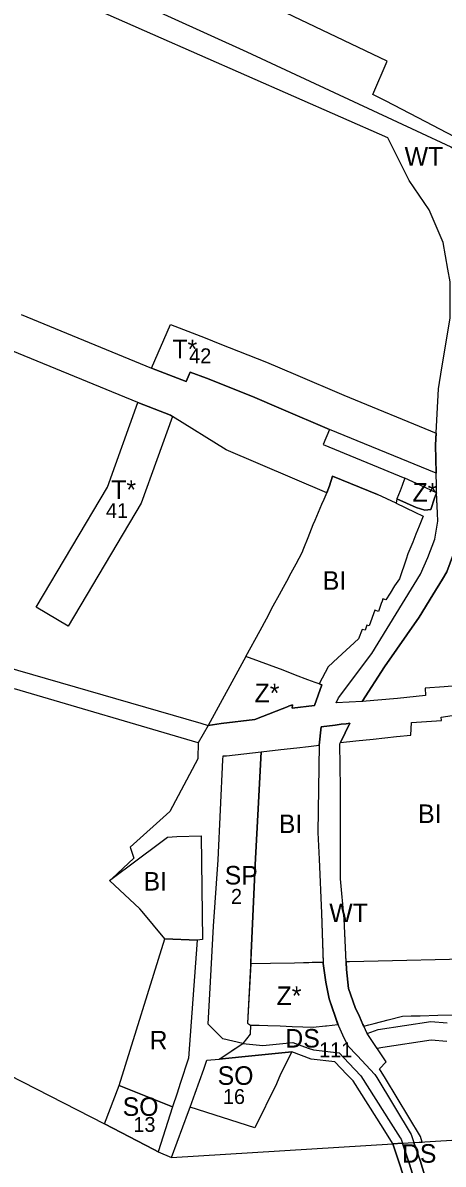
# Model space of a CAD drawing. Extents: x -521621 to -516769, y -1190068 to -1185078.
# Drawn here: x -520203 to -519977, y -1187500 to -1186885 of the extents above; entities that cross this region are included whole.
import ezdxf

# ---------------------------------------------------------------- set-up
doc = ezdxf.new("R2010")
doc.units = 0
for name, color, linetype in [('bydleni_s', 7, 'Continuous'), ('fpl_id', 7, 'Continuous'), ('rekreace_s', 7, 'Continuous'), ('s_zelen_s', 7, 'Continuous'), ('sm_vyuziti_n', 7, 'Continuous'), ('v_infrastr_n', 7, 'Continuous'), ('v_infrastr_s', 7, 'Continuous'), ('voda_s', 7, 'Continuous')]:
    doc.layers.add(name, color=color, linetype=linetype)

msp = doc.modelspace()

# ---------------------------------------------------------------- linework, layer by layer
at = {"layer": 'bydleni_s'}
for p, q in [((-519995.52, -1187170.82), (-519996.45, -1187173.61)), ((-520062.6, -1187188.74), (-520060.79, -1187185.41)), ((-520002.68, -1187187.93), (-520005.12, -1187191.92)), ((-520022.2, -1187216.47), (-520033.21, -1187226.78)), ((-520043.4, -1187240.82), (-520045.38, -1187240.09)), ((-520023.56, -1187271.54), (-520014.27, -1187270.57)), ((-520014.27, -1187270.57), (-520001.7, -1187269.26)), ((-520001.7, -1187269.26), (-519993.91, -1187268.44)), ((-520077.74, -1187338.31), (-520075.98, -1187304.68))]:
    msp.add_line(p, q, dxfattribs=at)
for points in [[(-520052.48, -1187170.02), (-520051.52, -1187167.64), (-520049.24, -1187161.96), (-520046.54, -1187155.01), (-520045.46, -1187152.58), (-520041.85, -1187144.05), (-520040.71, -1187141.36), (-520039.62, -1187138.78), (-520037.66, -1187134.14), (-520036.08, -1187128.81), (-520011.85, -1187138.77)], [(-519991.84, -1187148.2), (-519987.24, -1187150.36), (-519989.45, -1187155.81), (-519991.19, -1187160.12)], [(-519991.19, -1187160.12), (-519992.91, -1187164.38), (-519995.52, -1187170.82)], [(-519976.92, -1187184.39), (-519974.6, -1187180.49), (-519967.44, -1187161.06), (-519964.45, -1187159.95)], [(-520058.38, -1187180.94), (-520055.75, -1187176.08), (-520052.48, -1187170.02)], [(-519996.45, -1187173.61), (-519999.98, -1187184.21), (-520002.68, -1187187.93)], [(-520060.79, -1187185.41), (-520060.79, -1187185.41), (-520058.38, -1187180.94)], [(-519982.08, -1187192.81), (-519976.92, -1187184.39)], [(-520062.74, -1187233.45), (-520082.78, -1187226.03), (-520075.16, -1187212), (-520071.75, -1187205.69), (-520068.02, -1187198.79), (-520064.75, -1187192.74), (-520062.6, -1187188.74)], [(-520005.12, -1187191.92), (-520007.33, -1187195.55), (-520009.09, -1187194.99), (-520009.46, -1187196.2)], [(-520009.46, -1187196.2), (-520009.9, -1187197.54), (-520011.32, -1187201.87), (-520013.37, -1187201.13)], [(-519989.47, -1187204.85), (-519982.08, -1187192.81)], [(-520013.37, -1187201.13), (-520016.34, -1187209.5), (-520017.65, -1187209.12), (-520018.58, -1187211.91), (-520020.16, -1187211.54), (-520022.2, -1187216.47)], [(-520008.16, -1187231.72), (-519989.47, -1187204.85)], [(-520033.21, -1187226.78), (-520038.38, -1187231.62), (-520043.4, -1187240.82)], [(-520045.38, -1187240.09), (-520049.49, -1187238.6), (-520056.14, -1187236.18), (-520062.74, -1187233.45)], [(-520001.09, -1187248.72), (-520020.12, -1187250.41), (-520008.16, -1187231.72)], [(-519986.28, -1187243.18), (-519985.96, -1187247.03), (-520001.09, -1187248.72)], [(-519976.06, -1187242.43), (-519986.28, -1187243.18)], [(-519977.48, -1187260.57), (-519977.63, -1187258.79), (-519964.67, -1187256.87)], [(-519993.91, -1187268.44), (-519993.6, -1187261.65), (-519977.48, -1187260.57)], [(-520031.82, -1187333.95), (-520031.88, -1187296.91), (-520032.11, -1187273.07), (-520031.78, -1187272.4), (-520023.56, -1187271.54)], [(-520075.98, -1187304.68), (-520075.98, -1187304.68), (-520074.47, -1187277.44), (-520063.98, -1187276.25)], [(-520063.98, -1187276.25), (-520055.4, -1187275.27), (-520049, -1187274.54)], [(-520049, -1187274.54), (-520043.26, -1187273.88), (-520044.03, -1187320.95), (-520043.37, -1187335.34)], [(-520154.87, -1187345.66), (-520129.41, -1187326.7), (-520124.93, -1187323.53), (-520119.96, -1187323.11), (-520106.84, -1187322.8), (-520106.45, -1187351)], [(-519928.48, -1187329.94), (-519927.32, -1187362.5), (-519925.74, -1187387.64), (-519950.01, -1187388.86), (-520026.94, -1187390.59)], [(-520069.46, -1187391.55), (-520080.18, -1187391.79), (-520079.87, -1187386.04), (-520077.74, -1187338.31)], [(-520043.37, -1187335.34), (-520042.02, -1187364.47), (-520041.12, -1187390.91)], [(-520026.94, -1187390.59), (-520028.75, -1187390.63), (-520029.79, -1187367.52), (-520031.8, -1187345.91), (-520031.82, -1187333.95)], [(-520138.59, -1187363.54), (-520139.86, -1187362), (-520156.34, -1187346.76), (-520154.87, -1187345.66)], [(-520106.45, -1187351), (-520106.07, -1187378.67), (-520109, -1187378.97), (-520126.44, -1187378.2), (-520138.59, -1187363.54)], [(-520056.6, -1187391.26), (-520069.46, -1187391.55)], [(-520041.12, -1187390.91), (-520056.6, -1187391.26)]]:
    msp.add_lwpolyline(points, dxfattribs=at)
at = {"layer": 'rekreace_s'}
msp.add_lwpolyline([(-520151.11, -1187457.31), (-520126.44, -1187378.2), (-520109, -1187378.97), (-520113.78, -1187442.56), (-520118.16, -1187456.2), (-520119.82, -1187461.37), (-520122.23, -1187468.86)], close=True, dxfattribs=at)
at = {"layer": 's_zelen_s'}
msp.add_line((-520082.78, -1187226.03), (-520103.06, -1187263.21), dxfattribs=at)
for points in [[(-519981.11, -1187140.81), (-519980.11, -1187137.79), (-519988.63, -1187133.88), (-519997.15, -1187129.97), (-519997.34, -1187130.46), (-519997.52, -1187130.94)], [(-519997.52, -1187130.94), (-519998.46, -1187133.42), (-519998.64, -1187133.89), (-519999.75, -1187136.84), (-520000.58, -1187139.01)], [(-520000.58, -1187139.01), (-520001.4, -1187141.18)], [(-520001.4, -1187141.18), (-519991.04, -1187145.71), (-519986.33, -1187147.13), (-519983.12, -1187146.86), (-519981.11, -1187140.81)], [(-520103.06, -1187263.21), (-520096.08, -1187262.17), (-520077.9, -1187259.98), (-520066.44, -1187255.49), (-520060, -1187252.97), (-520059.76, -1187252.88), (-520057.72, -1187252.08), (-520057.81, -1187253.94), (-520045.91, -1187252.54), (-520041.82, -1187241.39), (-520043.4, -1187240.82), (-520045.38, -1187240.09), (-520049.49, -1187238.6), (-520056.14, -1187236.18), (-520062.74, -1187233.45), (-520082.78, -1187226.03)], [(-519925.74, -1187387.64), (-519950.01, -1187388.86), (-520026.94, -1187390.59)], [(-520080.18, -1187391.79), (-520081.88, -1187423.69), (-520080.26, -1187424.69)], [(-520069.46, -1187391.55), (-520080.18, -1187391.79)], [(-520056.6, -1187391.26), (-520069.46, -1187391.55)], [(-520047.12, -1187391.05), (-520056.6, -1187391.26)], [(-520033.27, -1187424.46), (-520033.18, -1187424.47), (-520038.01, -1187410.61), (-520039.71, -1187401.51), (-520041.1, -1187391.48), (-520041.12, -1187390.91), (-520047.12, -1187391.05)], [(-520026.94, -1187390.59), (-520028.75, -1187390.63)], [(-520028.75, -1187390.63), (-520028.56, -1187394.83), (-520027.48, -1187405.02), (-520023.85, -1187415.2), (-520021.62, -1187420.14), (-520019.74, -1187424.33), (-520019.29, -1187425.32)], [(-520019.29, -1187425.32), (-520016.5, -1187424.59), (-520013.71, -1187423.87), (-520006.09, -1187421.89), (-519998.46, -1187419.91), (-519993.67, -1187419.79), (-519988.89, -1187419.68), (-519979.39, -1187419.45), (-519969.88, -1187419.22)], [(-520080.26, -1187424.69), (-520075.65, -1187424.83), (-520071.03, -1187424.98), (-520064.4, -1187425.2), (-520057.77, -1187425.41), (-520052.11, -1187425.59), (-520046.46, -1187425.77), (-520039.86, -1187425.11), (-520039.4, -1187425.07)], [(-520039.4, -1187425.07), (-520033.27, -1187424.46)]]:
    msp.add_lwpolyline(points, dxfattribs=at)
at = {"layer": 'sm_vyuziti_n'}
for points in [[(-520103.02, -1187424.15), (-520101.79, -1187401.47), (-520100.32, -1187371.37), (-520097.7, -1187335.57), (-520095.26, -1187281.75), (-520094.96, -1187279.59), (-520093.26, -1187279.59), (-520074.47, -1187277.44), (-520075.98, -1187304.68), (-520077.74, -1187338.31), (-520079.87, -1187386.04), (-520081.88, -1187423.69), (-520080.26, -1187424.69), (-520080.41, -1187429.63), (-520084.35, -1187434.57), (-520095.15, -1187432.18)], [(-520159, -1187477.9), (-520151.11, -1187457.31), (-520122.23, -1187468.86), (-520129.99, -1187493.02), (-520132.3, -1187491.79)]]:
    msp.add_lwpolyline(points, close=True, dxfattribs=at)
for points in [[(-520084.9, -1187441.83), (-520058.07, -1187439.16), (-520064.09, -1187451.2), (-520066.25, -1187456.45), (-520077.97, -1187480.04), (-520112.8, -1187468.95), (-520110.1, -1187461.43)], [(-520110.1, -1187461.43), (-520105.47, -1187448.5), (-520103.75, -1187443.71), (-520097.11, -1187443.05), (-520084.9, -1187441.83)]]:
    msp.add_lwpolyline(points, dxfattribs=at)
at = {"layer": 'v_infrastr_n'}
for p, q in [((-520093.34, -1187114.72), (-520122.36, -1187096.77)), ((-520039.2, -1187137.79), (-520093.34, -1187114.72)), ((-520036.08, -1187128.81), (-520037.66, -1187134.14)), ((-520037.66, -1187134.14), (-520039.2, -1187137.79))]:
    msp.add_line(p, q, dxfattribs=at)
for points in [[(-520203.84, -1187041.77), (-520133.61, -1187070.63), (-520114.98, -1187077.93), (-520112.74, -1187072.75), (-520104.09, -1187076.15), (-520079.22, -1187085.96), (-520063.84, -1187092.51), (-520037.69, -1187103.65), (-520041.14, -1187111.86), (-519997.15, -1187129.97), (-519997.34, -1187130.46), (-519997.52, -1187130.94), (-519998.46, -1187133.42)], [(-520122.36, -1187096.77), (-520123.45, -1187096.09), (-520140.91, -1187089.25), (-520212.35, -1187059.89)], [(-520001.85, -1187143.49), (-520011.85, -1187138.77), (-520036.08, -1187128.81)], [(-519998.46, -1187133.42), (-519998.64, -1187133.89), (-519999.75, -1187136.84), (-520000.58, -1187139.01), (-520001.4, -1187141.18), (-520001.85, -1187143.49)], [(-520848.97, -1187150.16), (-520815.24, -1187153.86), (-520804.3, -1187155.06), (-520795.33, -1187156.04), (-520786.18, -1187157.04), (-520784.85, -1187157.19), (-520159, -1187477.9), (-520132.3, -1187491.79), (-520129.99, -1187493.02), (-520122.89, -1187496.11), (-520003.64, -1187488.76), (-519999.44, -1187501.15), (-519986.81, -1187542.36), (-519985.87, -1187549.88), (-519983.1, -1187579.65), (-519979.33, -1187615.33), (-519966.43, -1187650.48), (-519963.31, -1187658.97), (-520250.83, -1187655.58), (-520830.3, -1187354.88)], [(-519974.58, -1187433.59), (-519982.91, -1187432.87), (-520009.06, -1187436.87), (-520012.04, -1187437.34), (-520017.52, -1187429.25), (-520011.47, -1187427.12), (-519983.23, -1187422.8), (-519974.43, -1187423.57)], [(-520028.41, -1187451.33), (-520034.9, -1187444.46), (-520047.58, -1187443.02), (-520058.07, -1187439.16), (-520084.9, -1187441.83), (-520097.11, -1187443.05), (-520084.35, -1187434.57), (-520073.6, -1187435.68), (-520057.42, -1187434.07), (-520049.22, -1187437.09), (-520046.42, -1187438.12), (-520032.51, -1187439.69), (-520027.25, -1187445.29), (-520020.79, -1187452.11)], [(-520003.64, -1187488.76), (-520003.78, -1187488.36), (-520008.9, -1187480.27), (-520025.01, -1187454.78), (-520028.41, -1187451.33)], [(-520020.79, -1187452.11), (-520004.67, -1187477.59), (-519999.7, -1187485.45), (-519999.23, -1187486.19), (-519998.47, -1187488.44), (-520003.64, -1187488.76)], [(-519976.01, -1187540.05), (-519988.97, -1187497.77), (-519992.26, -1187488.06), (-519790.94, -1187475.66), (-519421.47, -1187513.5)], [(-520003.64, -1187488.76), (-519998.47, -1187488.44)], [(-519998.47, -1187488.44), (-519994.68, -1187499.61), (-519981.9, -1187541.31), (-519980.9, -1187549.34), (-519978.12, -1187579.15), (-519974.42, -1187614.19), (-519961.73, -1187648.76), (-519957.78, -1187659.54), (-519963.31, -1187658.97), (-519966.43, -1187650.48), (-519979.33, -1187615.33), (-519983.1, -1187579.65), (-519985.87, -1187549.88), (-519986.81, -1187542.36), (-519999.44, -1187501.15), (-520003.64, -1187488.76)]]:
    msp.add_lwpolyline(points, dxfattribs=at)
for points in [[(-520133.61, -1187070.63), (-520123.44, -1187047.07), (-520104.81, -1187054.38), (-520096.76, -1187057.54), (-520071.63, -1187067.45), (-520056, -1187074.11), (-520029.96, -1187085.21), (-519980.3, -1187105.65), (-519980.67, -1187112.17), (-519980.34, -1187127.26), (-520037.69, -1187103.65), (-520063.84, -1187092.51), (-520079.22, -1187085.96), (-520104.09, -1187076.15), (-520112.74, -1187072.75), (-520114.98, -1187077.93)], [(-520195.74, -1187199.54), (-520157.3, -1187134.81), (-520140.91, -1187089.25), (-520123.45, -1187096.09), (-520122.36, -1187096.77), (-520139.13, -1187143.38), (-520178.54, -1187209.75)], [(-519992.26, -1187488.06), (-519988.97, -1187497.77), (-519976.01, -1187540.05), (-519974.93, -1187548.69), (-519972.15, -1187578.56), (-519968.53, -1187612.82), (-519956.1, -1187646.69), (-519951.13, -1187660.22), (-519957.78, -1187659.54), (-519961.73, -1187648.76), (-519974.42, -1187614.19), (-519978.12, -1187579.15), (-519980.9, -1187549.34), (-519981.9, -1187541.31), (-519994.68, -1187499.61), (-519998.47, -1187488.44)]]:
    msp.add_lwpolyline(points, close=True, dxfattribs=at)
at = {"layer": 'v_infrastr_s'}
for p, q in [((-520103.06, -1187263.21), (-520108.49, -1187272.64)), ((-520043.26, -1187273.88), (-520042.21, -1187263.91)), ((-520031.42, -1187262.62), (-520028.82, -1187262.3)), ((-520028.82, -1187262.3), (-520026.72, -1187262.05)), ((-520093.26, -1187279.59), (-520074.47, -1187277.44)), ((-520074.47, -1187277.44), (-520063.98, -1187276.25)), ((-520063.98, -1187276.25), (-520055.4, -1187275.27)), ((-520055.4, -1187275.27), (-520049, -1187274.54)), ((-520049, -1187274.54), (-520043.26, -1187273.88))]:
    msp.add_line(p, q, dxfattribs=at)
for points in [[(-520006.7, -1186905.23), (-520068.84, -1186875.58)], [(-520014.43, -1186923.24), (-520006.7, -1186905.23)], [(-520007.61, -1186926.56), (-520014.43, -1186923.24)], [(-519860.1, -1187033.53), (-519863.94, -1187030.15), (-519913.58, -1186986.44), (-519930.08, -1186973.99), (-519949.41, -1186958.4), (-519970.36, -1186945.95), (-519989.93, -1186935.79), (-520007.61, -1186926.56)], [(-519918.52, -1187145.57), (-519930.8, -1187142.89), (-519944.87, -1187139.82), (-519956.35, -1187137.31), (-519956.45, -1187154.01), (-519923.46, -1187163.46), (-519921.77, -1187165.78), (-519928.79, -1187203.58), (-519929.56, -1187206.96), (-519931.27, -1187214.44), (-519931.99, -1187217.62), (-519932.26, -1187218.79), (-519931.87, -1187240.63), (-519938.01, -1187240.65), (-519948.74, -1187240.69), (-519952.63, -1187240.7), (-519967.83, -1187241.82), (-519971.63, -1187242.1), (-519976.06, -1187242.43), (-519986.28, -1187243.18), (-519985.96, -1187247.03), (-520001.09, -1187248.72), (-520020.12, -1187250.41)], [(-520001.4, -1187141.18), (-520001.85, -1187143.49)], [(-519986.33, -1187147.13), (-519991.04, -1187145.71), (-520001.4, -1187141.18)], [(-519981.11, -1187140.81), (-519983.12, -1187146.86)], [(-519980.11, -1187137.79), (-519981.11, -1187140.81)], [(-519979.97, -1187141.29), (-519980.11, -1187137.79)], [(-519979.66, -1187148.75), (-519979.97, -1187141.29)], [(-520034.16, -1187251.02), (-520032.92, -1187248.3), (-520015.02, -1187224.53), (-519988.78, -1187181.79), (-519984.81, -1187172.8), (-519980.95, -1187162.77), (-519979.48, -1187153.12), (-519979.66, -1187148.75)], [(-520001.85, -1187143.49), (-519991.84, -1187148.2), (-519987.24, -1187150.36)], [(-519983.12, -1187146.86), (-519986.33, -1187147.13)], [(-519987.24, -1187150.36), (-519989.45, -1187155.81), (-519991.19, -1187160.12), (-519992.91, -1187164.38), (-519995.52, -1187170.82), (-519996.45, -1187173.61), (-519999.98, -1187184.21), (-520002.68, -1187187.93), (-520005.12, -1187191.92), (-520007.33, -1187195.55), (-520009.09, -1187194.99), (-520009.46, -1187196.2), (-520009.9, -1187197.54), (-520011.32, -1187201.87), (-520013.37, -1187201.13), (-520016.34, -1187209.5), (-520017.65, -1187209.12), (-520018.58, -1187211.91), (-520020.16, -1187211.54), (-520022.2, -1187216.47), (-520033.21, -1187226.78), (-520038.38, -1187231.62), (-520043.4, -1187240.82), (-520041.82, -1187241.39), (-520045.91, -1187252.54), (-520057.81, -1187253.94), (-520057.72, -1187252.08), (-520059.76, -1187252.88)], [(-520258.7, -1187218.09), (-520107.14, -1187261.94)], [(-520108.49, -1187272.64), (-520207.51, -1187243.56)], [(-520060, -1187252.97), (-520066.44, -1187255.49), (-520077.9, -1187259.98)], [(-520059.76, -1187252.88), (-520060, -1187252.97)], [(-520020.12, -1187250.41), (-520034.16, -1187251.02)], [(-520026.72, -1187262.05), (-520031.78, -1187272.4), (-520023.56, -1187271.54), (-520014.27, -1187270.57), (-520001.7, -1187269.26), (-519993.91, -1187268.44), (-519993.6, -1187261.65), (-519977.48, -1187260.57), (-519977.63, -1187258.79), (-519964.67, -1187256.87)], [(-520107.14, -1187261.94), (-520103.06, -1187263.21), (-520108.49, -1187272.64)], [(-520077.9, -1187259.98), (-520096.08, -1187262.17), (-520103.06, -1187263.21)], [(-520042.21, -1187263.91), (-520034.62, -1187263)], [(-520034.62, -1187263), (-520031.42, -1187262.62)], [(-520108.49, -1187272.64), (-520108.68, -1187280.83)], [(-520108.69, -1187281.29), (-520123.82, -1187309.68)], [(-520108.68, -1187280.83), (-520108.69, -1187281.29)], [(-520084.35, -1187434.57), (-520095.15, -1187432.18), (-520103.02, -1187424.15), (-520101.79, -1187401.47), (-520100.32, -1187371.37), (-520097.7, -1187335.57), (-520095.26, -1187281.75)], [(-520095.26, -1187281.75), (-520094.96, -1187279.59), (-520093.26, -1187279.59)], [(-520123.82, -1187309.68), (-520145.11, -1187328.82)], [(-520142.14, -1187336.18), (-520129.41, -1187326.7), (-520124.93, -1187323.53), (-520119.96, -1187323.11)], [(-520119.96, -1187323.11), (-520106.84, -1187322.8), (-520106.45, -1187351), (-520106.07, -1187378.67), (-520109, -1187378.97), (-520113.78, -1187442.56), (-520118.16, -1187456.2), (-520119.82, -1187461.37), (-520122.23, -1187468.86), (-520129.99, -1187493.02)], [(-520145.11, -1187328.82), (-520143.11, -1187334.68)], [(-520143.11, -1187334.68), (-520154.87, -1187345.66)], [(-520154.87, -1187345.66), (-520142.14, -1187336.18)], [(-520090.5, -1187438.66), (-520088.87, -1187437.58)], [(-520088.87, -1187437.58), (-520088.19, -1187437.12)], [(-520088.19, -1187437.12), (-520084.35, -1187434.57)], [(-520112.8, -1187468.95), (-520110.1, -1187461.43), (-520105.47, -1187448.5), (-520103.75, -1187443.71), (-520097.11, -1187443.05)], [(-520097.11, -1187443.05), (-520090.73, -1187438.81)], [(-520090.73, -1187438.81), (-520090.5, -1187438.66)], [(-520090.5, -1187438.66), (-520090.5, -1187438.66)], [(-520122.89, -1187496.11), (-520113.63, -1187471.26)], [(-520113.63, -1187471.26), (-520112.8, -1187468.95)], [(-520129.99, -1187493.02), (-520122.89, -1187496.11)]]:
    msp.add_lwpolyline(points, dxfattribs=at)
at = {"layer": 'voda_s'}
for p, q in [((-519979.66, -1187148.75), (-519979.66, -1187148.75)), ((-520028.82, -1187262.3), (-520031.42, -1187262.62)), ((-520026.72, -1187262.05), (-520028.82, -1187262.3))]:
    msp.add_line(p, q, dxfattribs=at)
for points in [[(-519994.79, -1186969.47), (-520006.39, -1186946.62), (-520132.95, -1186890.9), (-520241.59, -1186842.91), (-520374.47, -1186784.03), (-520377.11, -1186789.47), (-520380.62, -1186787.87), (-520380.62, -1186787.87), (-520388.7, -1186784.19), (-520389.7, -1186783.73), (-520405.68, -1186776.45), (-520407.53, -1186775.61), (-520464.3, -1186749.75), (-520460.61, -1186741.14), (-520501.91, -1186716.18), (-520580.31, -1186676.98), (-520602.11, -1186673.29), (-520611.25, -1186667.48), (-520621.44, -1186657.47), (-520640.95, -1186650.79), (-520650.62, -1186653.07), (-520652.23, -1186652.29)], [(-520317.35, -1186794.57), (-520183.23, -1186854.16), (-520082.33, -1186900.21), (-519990.94, -1186942.77), (-519990.94, -1186942.77), (-519972.47, -1186951.37), (-519950.32, -1186964.73), (-519911.12, -1186993.2), (-519867.23, -1187034.17), (-519863.47, -1187037.69), (-519821.12, -1187077.22), (-519809.35, -1187086.01), (-519777.18, -1187107.81), (-519749.23, -1187125.56), (-519729.72, -1187137.52), (-519713.37, -1187145.6), (-519684.37, -1187157.2), (-519662.4, -1187164.59), (-519633.74, -1187171.44), (-519582.24, -1187178.82), (-519519.49, -1187187.61)], [(-519973.95, -1187017.39), (-519976.57, -1187003.02), (-519984.11, -1186985.31), (-519994.79, -1186969.47)], [(-519979.66, -1187148.75), (-519980.11, -1187137.79), (-519980.19, -1187134.19), (-519980.67, -1187112.17), (-519978.95, -1187081.91), (-519977.27, -1187070.47), (-519972.76, -1187043.74), (-519972.72, -1187024.12), (-519973.95, -1187017.39)], [(-519963.72, -1187086.02), (-519966.79, -1187110.48), (-519966.72, -1187139.73), (-519966.7, -1187145.62), (-519967.44, -1187161.06), (-519974.6, -1187180.49), (-519976.92, -1187184.39), (-519982.08, -1187192.81), (-519989.47, -1187204.85), (-520008.16, -1187231.72), (-520020.12, -1187250.41)], [(-519979.48, -1187153.12), (-519979.66, -1187148.75)], [(-519980.95, -1187162.77), (-519979.48, -1187153.12)], [(-519984.81, -1187172.8), (-519980.95, -1187162.77)], [(-519988.78, -1187181.79), (-519984.81, -1187172.8)], [(-520015.02, -1187224.53), (-519988.78, -1187181.79)], [(-520032.92, -1187248.3), (-520015.02, -1187224.53)], [(-520034.15, -1187251.02), (-520032.92, -1187248.3)], [(-520020.12, -1187250.41), (-520034.15, -1187251.02)], [(-520042.21, -1187263.91), (-520043.26, -1187273.88), (-520044.03, -1187320.95), (-520043.37, -1187335.34), (-520042.02, -1187364.47), (-520041.1, -1187391.48), (-520039.71, -1187401.51), (-520038.01, -1187410.61), (-520032.95, -1187425.14), (-520030.66, -1187429.97), (-520027.86, -1187435.88), (-520022.89, -1187441.17), (-520013.28, -1187451.31)], [(-520034.62, -1187263), (-520042.21, -1187263.91)], [(-520031.42, -1187262.62), (-520034.62, -1187263)], [(-520031.78, -1187272.4), (-520026.72, -1187262.05)], [(-520010.81, -1187448.23), (-520007.15, -1187444.56), (-520017.52, -1187429.25), (-520019.29, -1187425.32), (-520019.74, -1187424.33), (-520021.62, -1187420.14), (-520023.85, -1187415.2), (-520027.48, -1187405.02), (-520028.56, -1187394.83), (-520029.79, -1187367.52), (-520031.8, -1187345.91), (-520031.82, -1187333.95), (-520031.88, -1187296.91), (-520032.11, -1187273.07), (-520031.78, -1187272.4)], [(-520007.67, -1187453.46), (-520010.81, -1187448.23)], [(-520013.28, -1187451.31), (-520012.27, -1187452.98)], [(-520012.27, -1187452.98), (-519993.76, -1187483.65), (-519992.26, -1187488.06), (-519987.81, -1187487.79), (-519988.78, -1187484.84), (-520007.67, -1187453.46)]]:
    msp.add_lwpolyline(points, dxfattribs=at)

# ---------------------------------------------------------------- texts
at = {"layer": 'bydleni_s'}
for p in [(-520041.36, -1187190.13), (-519990.01, -1187315.81), (-520065.02, -1187321.26), (-520137.89, -1187352.21)]:
    msp.add_text('BI', height=10, dxfattribs=at).set_placement(p)
at = {"layer": 'fpl_id'}
for s, p in [('42', (-520113.35, -1187068.01)), ('41', (-520158.16, -1187151.45)), ('2', (-520090.83, -1187359.37)), ('111', (-520043.35, -1187442.05)), ('16', (-520095.15, -1187467.23)), ('13', (-520143.39, -1187482.26))]:
    msp.add_text(s, height=8, dxfattribs=at).set_placement(p)
at = {"layer": 'rekreace_s'}
msp.add_text('R', height=10, dxfattribs=at).set_placement((-520134.68, -1187437.84))
at = {"layer": 's_zelen_s'}
for p in [(-519993.04, -1187142.61), (-520078.1, -1187250.74), (-520066.24, -1187413.91)]:
    msp.add_text('Z*', height=10, dxfattribs=at).set_placement(p)
at = {"layer": 'sm_vyuziti_n'}
for s, p in [('SP', (-520094.19, -1187348.95)), ('SO', (-520098.01, -1187456.92)), ('SO', (-520149.16, -1187473.65))]:
    msp.add_text(s, height=10, dxfattribs=at).set_placement(p)
at = {"layer": 'v_infrastr_n'}
for s, p in [('T*', (-520122.36, -1187065.36)), ('T*', (-520155.31, -1187141.15)), ('DS', (-520061.55, -1187436.82)), ('DS', (-519998.74, -1187498.9))]:
    msp.add_text(s, height=10, dxfattribs=at).set_placement(p)
at = {"layer": 'voda_s'}
for p in [(-519997.27, -1186961.55), (-520037.87, -1187369.24)]:
    msp.add_text('WT', height=10, dxfattribs=at).set_placement(p)

doc.saveas('drawing.dxf')
